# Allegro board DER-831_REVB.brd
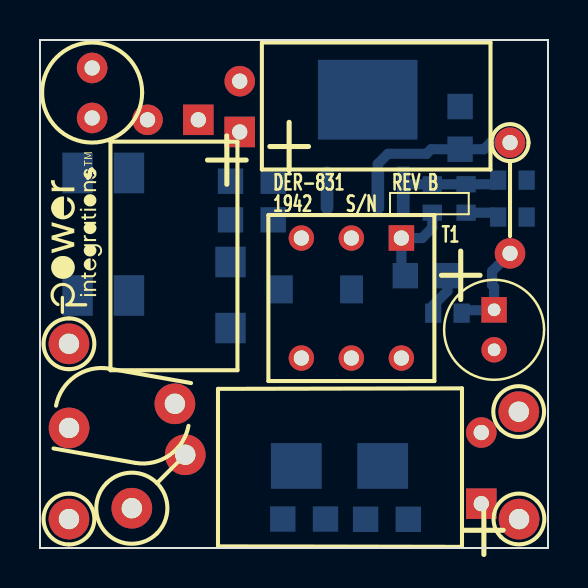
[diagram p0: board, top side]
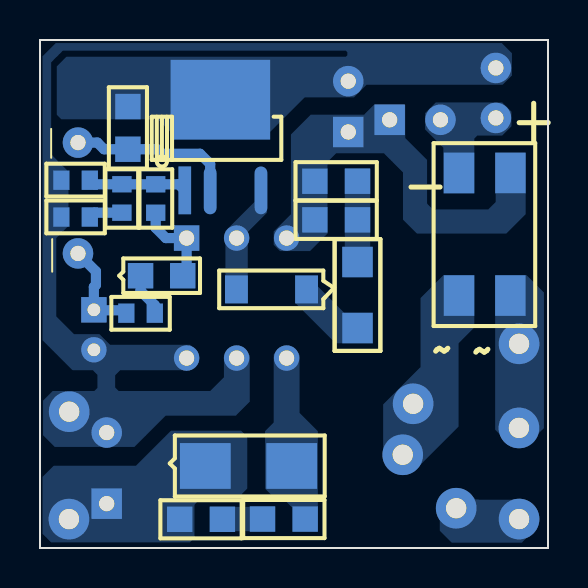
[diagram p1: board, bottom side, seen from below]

Outline 25.4 x 25.4 mm; copper layers: TOP, BOTTOM. Coordinates in mm from the lower left corner of the outline.
Outline path: 0,25.4 0,0 25.4,0 25.4,25.4 0,25.4

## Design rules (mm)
constraint set DEFAULT: min track width 0.508

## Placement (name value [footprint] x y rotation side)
BR1  B10S-G  [PISMSOIC4]  4.45 12.62 180 bottom
C1  2.2 uF  [PIPOLCAPCYLD250LS100030]  7.92 21.41 180 top
C2  2.2 uF  [PIPOLCAPCYLD250LS100030]  9.99 20.8 90 top
C3  10 uF  [PIPOLCAPCLYD5MMLS2MM025]  22.71 10.91 270 top
C4  1 uF  [PISMC0805]  21.01 19.94 90 bottom
C5  470 pF  [PISMC0805]  11.66 18.34 180 bottom
C6  680 pF  [PISMC0603]  22.91 16.55 0 bottom
C7  470 pF  [PISMC0805]  16.28 1.43 0 bottom
C8  470  uF  [PIPOLCAPCLYD320LS140030]  22.06 3.99 90 top
D2  BAV20WS-7-F  [PISMDSOD323]  20.37 13.61 180 bottom
D3  S1ML  [PI_SM_SOD-123_12]  12.07 12.93 0 bottom
D4  SS16-E3/61T  [PISMDO214AC12]  17.13 4.1 180 bottom
GND  BLK  [PITPKEYSTONE100X100]  23.94 6.82 315 top
L  WHT  [PITPKEYSTONE100X100]  1.45 1.45 0 top
L1  680 uH  [PICHOKETOKINVD216H413LS098D030]  2.61 21.5 90 top
N  BLK  [PITPKEYSTONE100X100]  1.45 10.21 0 top
NOREF  -  []  0 25.4 0 top
NOREF#2  -  []  0.64 11.15 90 top
NOREF#3  -  []  0 0 90 top
R1  100 k  [PISMR0805]  11.66 16.41 180 bottom
R2  301  [PISMR1206]  9.53 14.3 270 bottom
R3  20 k  [PISMR0603]  19.61 16.76 90 bottom
R4  4.87 k  [PISMR0603]  22.91 18.39 0 bottom
R5  24 k  [PI18WVRESD80LS100D030]  23.5 20.27 270 top
R6  10  [PISMR0603]  21.08 11.74 180 bottom
R7  47 k  [PISMR0603]  21.3 18.19 270 bottom
R8  15  [PISMR0805]  12.14 1.45 0 bottom
RF1  8.2  [PI12WRESD180LS575040]  4.59 1.99 45 top
RV1  300 Vac  [PI_DISC276X181_LS200X83D040]  6.38 5.13 170 top
T1  EE8.3  [PI_BOBBIN_EE8_3H6P]  15.57 12.5 270 top
U1  LNK623DG  [PISMSO8DNSHORT5678]  18.16 17.88 180 bottom
UNK+5V  RED  [PITPKEYSTONE100X100]  23.95 1.44 315 top

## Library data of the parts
BR1 = DIODE BRIDGE_~~+-: alternate symbols: (pi_sm_soic4_slot)
C1 C2 = CAP POL: alternate symbols: (pipolcapcyld250ls100030h)
C3 = CAP POL
C4-C7 = CAP NP
C8 = CAP POL: alternate symbols: (pipolcapclyd320ls140030430h)
D2 D3 = DIODE
D4 = DIODE SCHOTTKY
GND L N UNK+5V = TESTPOINT
L1 = INDUCTOR
R1-R4 R6-R8 = R
R5 = R: alternate symbols: (pi18wresd080ls300d030)
RF1 = RF: alternate symbols: (pi1wvresd120ls200d040)
RV1 = VARISTOR
T1 = BEE8_3_6P
U1 = LNK62X

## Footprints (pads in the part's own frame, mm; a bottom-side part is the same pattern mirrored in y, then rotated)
PI12WRESD180LS575040
  round 2.032 hole 1.016: 1(0,0) 2(3.78,0)
PI18WVRESD80LS100D030
  round 1.524 hole 0.762: 1(0,0) 2(5.54,0)
PI_BOBBIN_EE8_3H6P
  rect 1.27x1.27 hole 0.762: 1(-3,2.5)
  round 1.27 hole 0.762: 2(-3,0) 3(-3,-2.5) 4(3,-2.5) 5(3,0) 6(3,2.5)
PI_DISC276X181_LS200X83D040
  round 2.032 hole 1.016: 1(0,-2.108) 2(5.001,0)
PI_SM_SOD-123_12
  rect 1.143x1.397 smd: 1(0,0) 2(3.505,0)
PICHOKETOKINVD216H413LS098D030
  round 1.524 hole 0.762: 1(0,0) 2(2.5,0)
PIPOLCAPCLYD5MMLS2MM025
  rect 1.27x1.27 hole 0.635: 1(-1,0)
  round 1.27 hole 0.635: 2(1,0)
PIPOLCAPCLYD320LS140030
  rect 1.524x1.524 hole 0.762: 1(-1.778,0)
  round 1.524 hole 0.762: 2(1.778,0)
PIPOLCAPCYLD250LS100030
  rect 1.524x1.524 hole 0.762: 1(0,0)
  round 1.524 hole 0.762: 2(2.54,0)
PISMC0603
  rect 0.813x0.965 smd: 1(0,0) 2(1.422,0)
PISMC0805
  rect 1.27x1.27 smd: 1(0,0) 2(2.134,0)
PISMDO214AC12
  rect 2.54x2.286 smd: 1(0,0) 2(4.318,0)
PISMDSOD323
  rect 1.27x1.27 smd: 1(0,0) 2(2.108,0)
PISMR0603
  rect 0.813x0.965 smd: 1(0,0) 2(1.422,0)
PISMR0805
  rect 1.27x1.27 smd: 1(0,0) 2(2.134,0)
PISMR1206
  rect 1.524x1.524 smd: 1(0,0) 2(3.302,0)
PISMSO8DNSHORT5678
  rect 0.635x2.388 smd: 1(0,0)
  oval 0.635x2.388 smd: 2(1.27,0) 4(3.81,0) 5(3.81,4.978) 6(2.54,4.978) 7(1.27,4.978) 8(0,4.978)
PISMSOIC4
  rect 1.524x2.032 smd: 1(0,0) 2(2.571,0) 3(2.571,6.129) 4(0,6.129)
PITPKEYSTONE100X100
  round 2.032 hole 1.016: 1(0,0)

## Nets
SOURCE: U1.6 U1.7 U1.8
N02548: BR1.3 C1.1 C2.1 C5.1 R1.1 T1.3
N02667: C2.2 C3.2 C4.2 C6.2 C8.2 GND.1 L1.2 R4.2 T1.5 T1.6 U1.5(S)
N02674: BR1.4 C1.2 L1.1
N03548: C4.1 R5.1 U1.2
N03639: R3.2 R4.1 R7.1 U1.1
N04459: C3.1 R5.2 R6.1
N04496: D2.1 R6.2
N04748: D3.2 T1.2 U1.4
N04766: D2.2 R3.1 T1.1
N04877: D4.2 R8.1 T1.4
N04912: C7.1 R8.2
N04991: C7.2 C8.1 D4.1 UNK+5V.1
N06108: BR1.1 RF1.2 RV1.1
N06154: L.1 RF1.1
N06177: BR1.2 N.1 RV1.2
N12152: C5.2 R1.2 R2.1
N12184: D3.1 R2.2
N16271: C6.1 R7.2

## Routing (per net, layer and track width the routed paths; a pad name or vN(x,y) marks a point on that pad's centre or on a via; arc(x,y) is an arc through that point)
N03548: length 8.4
  BOTTOM w0.508: R5.1 22.53,20.27 22.2,19.94 C4.1 19.56,19.94 19.33,19.71 17.4,19.71 16.89,19.2 U1.2
N03639: length 5
  BOTTOM w0.508: U1.1 18.47,18.19 R3.2 21.3,18.19 R7.1 22.71,18.19 R4.1
N04459: length 4.9
  BOTTOM w0.508: R6.1 21.23,11.89 22.39,11.89 22.41,11.91 C3.1 22.71,13.05 22.6,13.16 22.6,13.83 R5.2
N04496: length 2.2
  BOTTOM w0.508: D2.1 20.37,12.85 19.66,12.14 R6.2
N04766: length 4.5
  BOTTOM w0.508: D2.2 18.07,13.81 T1.1 19.11,15.5 19.61,16.01 R3.1
N16271: length 1.7
  BOTTOM w0.508: C6.1 22.69,16.76 R7.2

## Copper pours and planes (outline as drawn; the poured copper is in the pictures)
N02548 on BOTTOM: 7.25,18.78 7.25,16.42 6.55,15.72 2.08,15.72 1.12,16.69 1.12,19.76 2.62,19.76 2.62,17.3 2.98,16.93 5.75,16.93 6.05,17.22 6.05,19.41 7.14,20.5 7.14,22.17 8.69,22.17 9.19,21.67 11.86,21.67 12.85,20.68 12.85,16.69 13.72,15.82 13.72,15.16 13.4,14.85 11.9,14.85 11.02,15.72 11.02,19.3 10.59,19.74 8.2,19.74
N02667 on BOTTOM (solid shape): 18.87,20.42 13.89,20.42 13.89,24.41 18.87,24.41
N02667 on BOTTOM: 20.68,5.05 19.11,6.62 15.61,6.62 14.91,7.32 14.91,9.63 15.32,10.03 15.82,10.03 16.21,9.65 16.21,8.53 16.89,7.85 21.46,7.85 21.64,8.03 21.64,8.64 21.39,8.89 17.91,8.89 17.54,9.26 17.54,9.82 17.88,10.16 21.89,10.16 22.43,10.69 23.7,10.69 24.59,11.58 24.59,15.49 23.98,16.1 23.98,18.82 24.84,19.68 24.84,24.28 24.26,24.87 10.11,24.87 10.03,24.79 10.03,24.64 10.11,24.56 24.08,24.56 24.56,24.08 24.56,21.67 24.33,21.44 19.51,21.44 18.87,20.8 13.89,20.8 12.17,22.53 9.7,22.53 9.07,23.16 2.26,23.16 1.8,23.62 1.8,24.74 2.31,25.25 24.61,25.25 25.27,24.59 25.27,10.39 23.77,8.89 22.76,8.89 22.53,8.66 22.53,8 22.68,7.85 24.77,7.85 25.25,7.37 25.25,5.64 24.66,5.05
N02674 on BOTTOM: 3.68,17.73 3.68,20.47 3.53,20.62 2.29,20.62 1.83,21.08 1.83,21.82 2.29,22.28 5.61,22.28 6.15,21.74 6.15,20.93 5.23,20.02 5.23,17.73
N04748 on BOTTOM: 14.05,18.72 14.05,16.76 15.01,15.8 15.01,12.24 16.13,12.24 16.13,15.85 14.66,17.32 14.66,18.72 14.5,18.87 14.2,18.87
N04877 on BOTTOM: 13.36,10.03 13.72,9.68 13.72,6.27 14.15,5.84 14.15,2.97 13.82,2.64 13.41,2.64 12.78,2.01 12.78,0.81 11.51,0.81 11.51,5.84 12.42,6.76 12.42,9.65 12.8,10.03
N04912 on BOTTOM: 13.67,0.84 16.89,0.84 16.89,2.06 13.67,2.06
N04991 on BOTTOM: 15.34,5.87 18.85,5.87 20.6,4.11 24.71,4.11 25.27,3.56 25.27,0.71 24.84,0.28 17.91,0.28 17.68,0.51 17.68,2.16 17.22,2.62 15.39,2.62 15.04,2.97 15.04,5.56
N06108 on BOTTOM: 6.38,9.04 6.38,12.5 5.23,13.64 3.68,13.64 3.68,11.02 4.47,10.24 4.47,6.07 6.65,3.89 7.62,3.89 8.24,4.51 8.24,7.18
N06154 on BOTTOM: 1.31,0.27 0.74,0.84 0.74,1.88 1.27,2.41 3.45,2.41 3.47,2.43 3.62,2.43 3.91,2.72 4.93,2.72 5.41,2.24 5.41,0.86 4.81,0.27
N06177 on BOTTOM: 0.2,12.78 1.07,13.64 2.64,13.64 2.64,5.92 2.08,5.36 0.84,5.36 0.2,5.99
N12152 on BOTTOM: 10.16,18.97 8.89,18.97 8.89,13.54 10.16,13.54
N12184 on BOTTOM: 12.62,13.61 11.51,13.61 11.51,13.08 10.19,11.76 8.76,11.76 8.76,10.24 10.62,10.24 12.62,12.24

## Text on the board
Ref Des/Silkscreen Top: DER-831 | 1942 | S/N | REV B
User.5: 1.  THROUGH HOLES ARE PLATED THROUGH. | EXCEPTIONS WILL BE NOTED IN DRILL CHART "NOTE". | 2.  MATERIAL: BASE MATERIAL LAMINATED EPOXY | UL APPROVED MANUFACTURED SOURCE FOR FR4. | 3.  SOLDER PLATE WILL BE RoHS COMPLIANT. | 4.  SOLDER MASK LPI (LIQUID PHOTO IMAGEABLE) BOTH SIDES. COLOR GREEN. | SOLDER MASK (REGISTRATION) -0/+0.003" | 5.  SILKSCREEN TOP/BOTTOM SIDE. COLOR WHITE. (MIN.WIDTH 0.005" MAX.WIDTH 0.010") | 6.  FINISH TO BE SMOBC. | 7.  LEAD FREE HASL (HOT AIR SOLDER LEVEL) OR RoHS COMPLIANT. | 8.  BOARD DIMENSION +/- 0.005" | 9.  DRILL TOLERANCE +/- 0.003" | 10. TRACE WIDTH UNDER 0.010" +/- 0.002" | TRACE WIDTH OVER 0.011" +/- 0.005" | 11. TRACE SPACE +/- 0.003" | 12. MATERIAL FR4 COPPER 2 OZ BOARD THICKNESS 0.062" | NOTES: UNLESS OTHERWISE SPECIFIED
User.8: FIGURE | FINISHED_SIZE | 30.0 | 40.0 | DRILL CHART: TOP to BOTTOM | ALL UNITS ARE IN MILS | PLATED | QTY | 18 | 8
